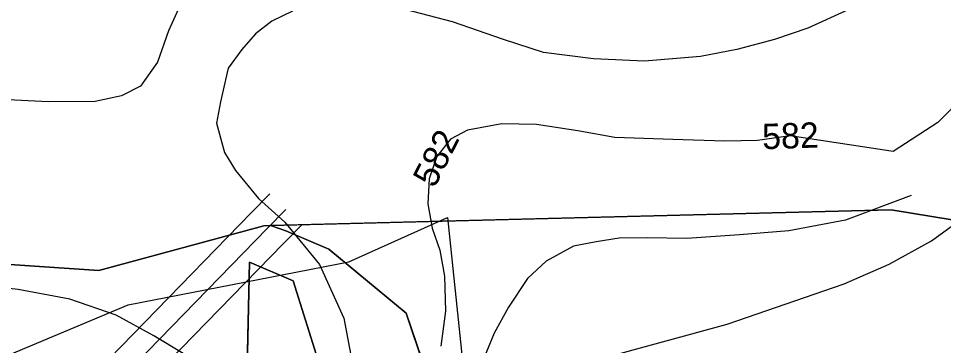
# Model space of a CAD drawing. Extents: x -709418 to -703832, y -1161719 to -1157826.
# Drawn here: x -706007.3 to -705715.8, y -1159236.4 to -1159133.3 of the extents above; entities that cross this region are included whole.
import ezdxf

# ---------------------------------------------------------------- set-up
doc = ezdxf.new("R2010")
doc.units = 0
for name, color, linetype in [('102_obvod PÚ', 7, 'Continuous'), ('103_hranice KÚ', 7, 'Continuous'), ('120_vrstevnice hlavní', 7, 'Continuous'), ('121_vrstevnice hlavní_popis', 7, 'Continuous'), ('122_vrstevnice základní', 7, 'Continuous'), ('124_vrstevnice doplňková', 7, 'Continuous'), ('206_TTP_KN', 7, 'Continuous'), ('207_lesní pozemek_KN', 7, 'Continuous'), ('514 odvodnění - LPIS', 7, 'Continuous'), ('708_el NN nadzemní a podzemní_ E.ON', 7, 'Continuous'), ('735_OP sítí TI', 7, 'Continuous')]:
    doc.layers.add(name, color=color, linetype=linetype)

msp = doc.modelspace()

# ---------------------------------------------------------------- linework, layer by layer
at = {"layer": '102_obvod PÚ'}
msp.add_lwpolyline([(-706044.43, -1159208.57), (-705981.99, -1159212.78), (-705930.01, -1159198.72), (-705927.86, -1159198.62), (-705732.21, -1159193.61), (-705680.34, -1159202.12)], dxfattribs=at)
at = {"layer": '103_hranice KÚ'}
msp.add_lwpolyline([(-705680.34, -1159202.12), (-705732.21, -1159193.61), (-705919.14, -1159198.4), (-705927.86, -1159198.62), (-705930.01, -1159198.72), (-705981.99, -1159212.78), (-706044.43, -1159208.57), (-706080.07, -1159188.89), (-706110.25, -1159179.64), (-706116.44, -1159178.27), (-706133.13, -1159179.42), (-706152.12, -1159184.17), (-706177.67, -1159162.96), (-706192.12, -1159167.94), (-706215.77, -1159161.38), (-706231.79, -1159158.33), (-706252.27, -1159161.78), (-706262.2, -1159161.19), (-706313.3, -1159137.18), (-706346.78, -1159114.03)], dxfattribs=at)
at = {"layer": '120_vrstevnice hlavní'}
for points in [[(-705911.32, -1159280.49), (-705915.39, -1159278.85), (-705921.87, -1159273.51), (-705931.22, -1159260.27), (-705939.07, -1159252.87), (-705948.1, -1159244.26), (-705955.44, -1159238.91), (-705964.66, -1159233.39), (-705976.47, -1159226.8), (-705991.17, -1159221.76), (-706007.43, -1159218.77), (-706023.18, -1159216.97), (-706044.71, -1159212.98), (-706057.2, -1159208.98), (-706067.96, -1159202.41), (-706076.99, -1159194.86), (-706089.95, -1159181.95), (-706106.32, -1159167.99), (-706122.53, -1159156.1), (-706176.41, -1159124.39)], [(-705920.89, -1159130.94), (-705927.42, -1159134.16), (-705932.58, -1159138.07), (-705936.88, -1159143.02), (-705941.19, -1159148.99), (-705943.64, -1159159.6), (-705944.88, -1159166.27), (-705942.35, -1159175.54), (-705938.96, -1159181.2), (-705931.66, -1159190.07), (-705923.38, -1159197.5), (-705912.38, -1159210.82), (-705904.76, -1159227.81), (-705902.26, -1159241.18), (-705903.19, -1159256.08), (-705905.49, -1159270.8), (-705907.92, -1159277.81), (-705909.71, -1159280.39)], [(-705745.61, -1159130.43), (-705758.56, -1159136.34), (-705769.02, -1159139.89), (-705780.86, -1159143.08), (-705792.34, -1159145.25), (-705809.99, -1159146.78), (-705826.09, -1159146.02), (-705841.83, -1159144.05), (-705854.49, -1159139.88), (-705870.56, -1159134.3), (-705885.44, -1159130.45)]]:
    msp.add_lwpolyline(points, dxfattribs=at)
at = {"layer": '122_vrstevnice základní'}
for points in [[(-705955.32, -1159126.68), (-705960.03, -1159137.18), (-705963.5, -1159147.1), (-705968.85, -1159154.61), (-705974.87, -1159157.67), (-705983.1, -1159159.51), (-705997.84, -1159159.61), (-706012.74, -1159158.85), (-706022.68, -1159159.15), (-706028.34, -1159158.78), (-706036.38, -1159156.68), (-706050.99, -1159149.28), (-706085.74, -1159127.54)], [(-705709.16, -1159157.55), (-705717.59, -1159166.06), (-705731.65, -1159175.24), (-705764.1, -1159170.3), (-705774.4, -1159171.73), (-705784.7, -1159172.01), (-705801.06, -1159171.4), (-705819.38, -1159170.8), (-705831, -1159168.69), (-705844, -1159166.74), (-705854.96, -1159166.52), (-705865.83, -1159168.49), (-705871.15, -1159171.37), (-705875.45, -1159176.83), (-705877.89, -1159183.84), (-705878.27, -1159191.71), (-705876.94, -1159199.42), (-705874.55, -1159206.38), (-705873.05, -1159214.6), (-705872.76, -1159225.56), (-705874.16, -1159236.6)], [(-705872.14, -1159294.88), (-705870.29, -1159286.75), (-705865.44, -1159274.63), (-705858.72, -1159265.08), (-705851.31, -1159255.36), (-705842.04, -1159248.4), (-705832.78, -1159243.65), (-705824.72, -1159240.78), (-705783.97, -1159229.69), (-705747.1, -1159217), (-705732.87, -1159210.74), (-705719.49, -1159203.45), (-705705.95, -1159193.52)]]:
    msp.add_lwpolyline(points, dxfattribs=at)
at = {"layer": '124_vrstevnice doplňková'}
msp.add_lwpolyline([(-705725.91, -1159189.13), (-705746.65, -1159196.9), (-705764.47, -1159200.23), (-705780.05, -1159201.52), (-705796.64, -1159202.68), (-705809.13, -1159202.45), (-705818.03, -1159202.58), (-705825.23, -1159203.74), (-705832.42, -1159205.07), (-705841, -1159209.82), (-705846.85, -1159215.27), (-705852.88, -1159224.31), (-705857.37, -1159232.5), (-705862.22, -1159244.29), (-705868.46, -1159260.86)], dxfattribs=at)
at = {"layer": '206_TTP_KN'}
for p, q in [((-705927.86, -1159198.62), (-705732.21, -1159193.61)), ((-705732.21, -1159193.61), (-705680.34, -1159202.12)), ((-705923.04, -1159200.26), (-705927.86, -1159198.62)), ((-705909.51, -1159206.01), (-705923.04, -1159200.26)), ((-705885.13, -1159226.22), (-705909.51, -1159206.01)), ((-705870.43, -1159269.46), (-705885.13, -1159226.22))]:
    msp.add_line(p, q, dxfattribs=at)
for points in [[(-706044.43, -1159208.57), (-705981.99, -1159212.78), (-705930.01, -1159198.72), (-705927.86, -1159198.62), (-705923.04, -1159200.26), (-705909.51, -1159206.01), (-705885.13, -1159226.22), (-705870.43, -1159269.46), (-705873.26, -1159314.73), (-705872.26, -1159352.55), (-705875.66, -1159340.81), (-705885.23, -1159315.13), (-705883.08, -1159289.91), (-705887.72, -1159264.42), (-705913.62, -1159263.09), (-705965.07, -1159270.08), (-705994.54, -1159270.79), (-706026.1, -1159306.74)], [(-705935.28, -1159243.55), (-705929.01, -1159254.91), (-705921.74, -1159258.27), (-705914.6, -1159253.2), (-705912.92, -1159240.82), (-705920.77, -1159215.99), (-705934.47, -1159210.14), (-705935.28, -1159243.55)]]:
    msp.add_lwpolyline(points, dxfattribs=at)
at = {"layer": '207_lesní pozemek_KN'}
for p, q in [((-705935.28, -1159243.55), (-705934.47, -1159210.14)), ((-705934.47, -1159210.14), (-705920.77, -1159215.99)), ((-705920.77, -1159215.99), (-705912.92, -1159240.82))]:
    msp.add_line(p, q, dxfattribs=at)
at = {"layer": '514 odvodnění - LPIS'}
msp.add_lwpolyline([(-706013.42, -1159240.57), (-705972.72, -1159223.59), (-705903.2, -1159210), (-705872.08, -1159196), (-705856.8, -1159342.91), (-705816.39, -1159382.97), (-705884.59, -1159400.56), (-705887.17, -1159444.28), (-705898.86, -1159471.82), (-705898.18, -1159492.12), (-705844.9, -1159501.19), (-705815.12, -1159494.2), (-705796.03, -1159508.47), (-705795.12, -1159533.4), (-705833.3, -1159552.97), (-705873.25, -1159615.85), (-705852.77, -1159626.96)], dxfattribs=at)
at = {"layer": '708_el NN nadzemní a podzemní_ E.ON'}
msp.add_lwpolyline([(-705998.69, -1159270.29), (-705996.6, -1159269.07), (-705928.93, -1159199.48), (-705923.07, -1159193.55)], dxfattribs=at)
at = {"layer": '735_OP sítí TI'}
for points in [[(-706002.22, -1159264.24), (-706000.95, -1159263.5), (-705933.93, -1159194.58), (-705928.04, -1159188.63)], [(-705995.17, -1159276.34), (-705992.25, -1159274.63), (-705923.93, -1159204.38), (-705918.09, -1159198.47)]]:
    msp.add_lwpolyline(points, dxfattribs=at)

# ---------------------------------------------------------------- texts
at = {"layer": '121_vrstevnice hlavní_popis'}
for rotation, p in [(1.7617, (-705772.81, -1159174.52)), (62.9651, (-705876.23, -1159187.04))]:
    msp.add_text('582', height=8, rotation=rotation, dxfattribs=at).set_placement(p)

doc.saveas('drawing.dxf')
